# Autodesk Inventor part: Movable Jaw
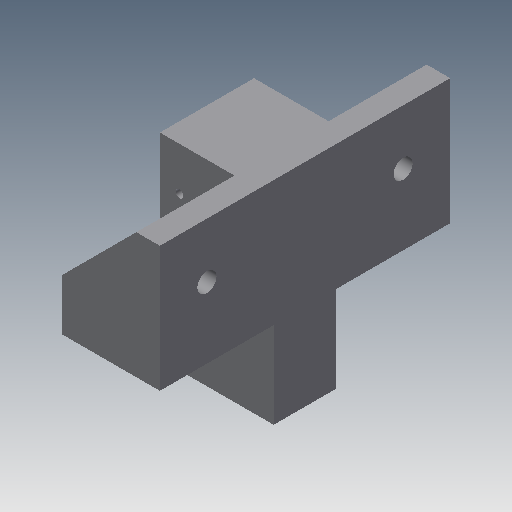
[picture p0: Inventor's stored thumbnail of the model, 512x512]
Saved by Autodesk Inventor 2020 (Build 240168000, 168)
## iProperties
Created: 2002-02
Part Number: Movable Jaw
Document SubType Name: Modeling
Designer: ***
Density: 1 g/cm^3
Material: Generic
Mass: 56.5588 g
Surface Area: 124.299 cm^2
Volume: 56.5588 cm^3
Appearance: Default
Control State: 0
Master: False
Checked Out: False
Shininess: 77.0
Length Units: 11269
Angle Units: 11279
Time Units: 11290
Mass Units: 11283
Length Display Precision: 3
Angle Display Precision: 2
Density: 0.0
Volumn: 0.0
Area: 0.0
PropertySet Name: Model Information
Author: ***
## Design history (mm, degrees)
sketch "Sketch2"
  geometry: L1 (2.39, 41.509)-(2.39, 9.509); L2 (2.39, 9.509)-(-22.61, 9.509); L3 (-22.61, 9.509)-(-22.61, 22.509); L4 (-22.61, 22.509)-(-3.61, 41.509); L5 (-3.61, 41.509)-(2.39, 41.509)
  constraints: 10 end point, 2 parallel, 1 perpendicular, 1 vertical
  dimensions: "d0" = 25 distance of L1.end L2.end; "d2" = 13 distance of L2.end L3.end; "d3" = 32 distance between parallel lines of L5 L2; "d4" = 6 distance of L4.end L1.start
extrude "Extrusion1" new body sketch "Sketch2" stored distance "d5" = 74; taper "d6" = 0 deg
sketch "Sketch3"
  geometry: L1 (-19, 25)-(11, 25); L2 (11, 25)-(11, 49); L3 (11, 49)-(-19, 49); L4 (-19, 49)-(-19, 25); L5 (0, 0)-(13, 0) reference; L6 (-19, 74)-(-19, 0) reference; L7 (11.924, 29)-(35, 29); L8 (35, 29)-(35, 45); L9 (35, 45)-(11.924, 45); L10 (11.924, 45)-(11.924, 29); L11 (13, 74)-(13, 0) reference
  constraints: 16 end point, 4 parallel, 2 horizontal, 2 perpendicular, 1 collinear
  dimensions: "d7" = 24 distance of L3.end L1.start; "d8" = 30 distance of L1.start L1.end; "d9" = 25 distance between parallel lines of L5 L1; "d10" = 16 distance of L7.end L8.end; "d11" = 4 distance between parallel lines of L3 L9; "d12" = 22 distance between parallel lines of L11 L8
extrude "Extrusion2" join sketch "Sketch3" distance "d13" = 25; taper "d14" = 0 deg
sketch "Sketch4"
  geometry: L1 (-19, -25)-(-19, -49) reference; L2 (-19, -49)-(0, -49) reference; 1 further point
  dimensions: "d15" = 11 distance from line of L1 point (-8, -37); "d16" = 12 distance from line of L2 point (-8, -37)
hole "Hole1" sketch "Sketch4" at (-8, -37) diameter "d17" = 10; stored, may be unused: countersink angle "d21" = 82 deg, drill point angle "d23" = 0 deg; dims "d18" = 6, "d19" = 4, "d20" = 2, "d22" = 13
sketch "Sketch5"
  geometry: L1 (-19, -49)-(-19, -74) reference; L2 (0, -74)-(13, -74) reference; 1 further point
  dimensions: "d24" = 14 distance from line of L1 point (-5, -62); "d25" = 12 distance from line of L2 point (-5, -62)
hole "Hole2" sketch "Sketch5" at (-5, -62) diameter "d26" = 4.917; stored, may be unused: countersink angle "d30" = 82 deg, drill point angle "d32" = 0 deg; dims "d27" = 12, "d28" = 8, "d29" = 10, "d31" = 17.1
mirror "Mirror1"
sketch "Sketch6"
  geometry: L1 (0, 19)-(0, 0) reference; 1 further point
  dimensions: "d33" = 5 distance from line of L1 point (-5, 8); "d34" = 11 vertical distance of L1.start point (-5, 8)
hole "Hole3" sketch "Sketch6" at (-5, 8) diameter "d35" = 2; stored, may be unused: countersink angle "d39" = 82 deg, drill point angle "d41" = 0 deg; dims "d36" = 6, "d37" = 8, "d38" = 10, "d40" = 13
body "Solid1"
